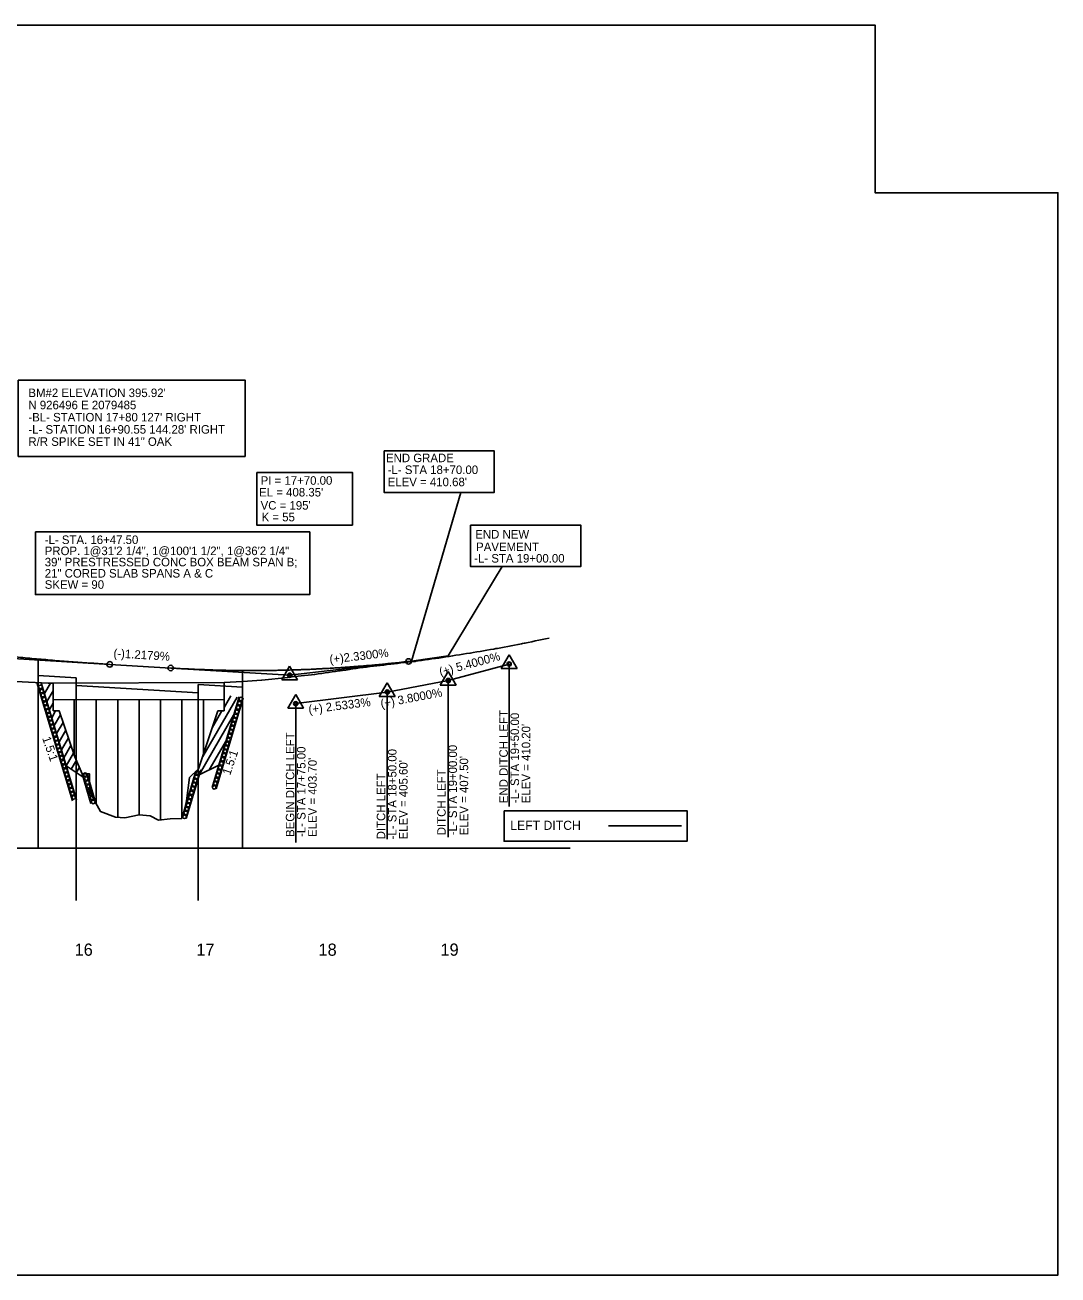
# Model space of a CAD drawing. Extents: x 573767 to 575255, y -54545 to -52045.
# Drawn here: x 574408 to 575255, y -53645 to -52620 of the extents above; entities that cross this region are included whole.
import ezdxf

# ---------------------------------------------------------------- set-up
doc = ezdxf.new("R2010")
doc.units = 0
for name, color, linetype in [('Default', 7, 'Continuous'), ('Exist Vertical Profile Ground Line', 7, 'Continuous'), ('Exist Vertical Profile Horizontal Axis Label Major', 7, 'Continuous'), ('Old_Level_2', 7, 'Continuous'), ('Old_Level_4', 7, 'Continuous'), ('Old_Level_63', 7, 'Continuous'), ('Prop Grid Mask', 7, 'Continuous'), ('Prop PFL Ditch Label CELL', 7, 'Continuous'), ('Prop PFL VPI Symbol CELL', 7, 'Continuous'), ('Prop Roadway Bridge', 7, 'Continuous'), ('Prop Vertical Profile Curve Label', 7, 'Continuous'), ('Prop Vertical Profile Ditch Grade Left', 7, 'Continuous'), ('Prop Vertical Profile Ditch Grade Left Label', 7, 'Continuous'), ('Prop Vertical Profile Grade', 7, 'Continuous'), ('Prop Vertical Profile Grade Label', 7, 'Continuous'), ('Prop VPI Ditch Grade Left Label', 7, 'Continuous'), ('Prop VPI Label', 7, 'Continuous'), ('Sheet Layout Profile Border', 7, 'Continuous')]:
    doc.layers.add(name, color=color, linetype=linetype)

msp = doc.modelspace()

# ---------------------------------------------------------------- linework, layer by layer
at = {"layer": 'Default'}
for p, q in [((574423.8, -53167.9), (574428.7, -53159.3)), ((574425.7, -53174.5), (574430.8, -53165.8)), ((574427.7, -53181.1), (574430.8, -53175.8)), ((574553.5, -53219.5), (574581.6, -53170.8)), ((574570.9, -53179.3), (574576.5, -53169.7)), ((574429.7, -53187.7), (574432.8, -53182.2)), ((574431.7, -53194.2), (574436.8, -53185.3)), ((574550.6, -53234.5), (574578.8, -53185.6)), ((574561.3, -53195.9), (574569.2, -53182.2)), ((574433.6, -53200.8), (574439, -53191.6)), ((574435.6, -53207.4), (574441.1, -53197.8)), ((574437.6, -53214), (574443.3, -53204.1)), ((574558.7, -53230.5), (574572.8, -53206.1)), ((574439.6, -53220.6), (574445.4, -53210.4)), ((574441.5, -53227.1), (574447.6, -53216.7)), ((574445.7, -53230), (574449.9, -53222.5)), ((574449.8, -53232.8), (574452.4, -53228.4)), ((574454, -53235.6), (574454.8, -53234.2))]:
    msp.add_line(p, q, dxfattribs=at)
at = {"layer": 'Exist Vertical Profile Ground Line'}
for p, q in [((574430.8, -53159.3), (574570.9, -53158.8)), ((574430.8, -53182.2), (574430.8, -53159.3)), ((574570.9, -53182.2), (574570.9, -53158.8)), ((574430.8, -53172.7), (574570.9, -53173)), ((574447.9, -53217.5), (574447.9, -53172.7)), ((574466.1, -53258.2), (574466.1, -53172.8)), ((574483.9, -53269.5), (574483.9, -53172.8)), ((574501.2, -53267.3), (574501.2, -53172.8)), ((574518.7, -53271.5), (574518.7, -53172.9)), ((574536.3, -53270.4), (574536.3, -53172.9)), ((574554.2, -53217.2), (574554.2, -53173))]:
    msp.add_line(p, q, dxfattribs=at)
for points in [[(574680.6, -53147.2), (574682.1, -53146.9), (574684.9, -53146.6), (574687.1, -53146.3), (574687.2, -53146.2), (574687.7, -53146.2), (574690.6, -53145.8), (574693.4, -53145.5), (574696.2, -53145.2), (574699, -53144.8), (574701.9, -53144.5), (574704.7, -53144.2), (574707.3, -53143.9), (574707.5, -53143.9), (574707.7, -53143.8), (574710.3, -53143.5), (574713.2, -53143.2), (574716, -53142.8), (574718.8, -53142.5), (574721.6, -53142.2), (574724.4, -53141.9), (574727.3, -53141.5), (574727.6, -53141.5), (574728.2, -53141.4), (574730.1, -53141.1), (574732.9, -53140.7), (574735.7, -53140.3), (574738.6, -53139.9), (574741.4, -53139.5), (574744.2, -53139.2), (574747, -53138.8), (574749.8, -53138.4), (574749.9, -53138.4), (574750.7, -53138.2), (574751.5, -53138.1), (574752.7, -53137.9), (574755.5, -53137.4), (574758.3, -53137), (574761.1, -53136.5), (574764, -53136.1), (574766.8, -53135.7), (574769.6, -53135.2), (574772.4, -53134.8), (574773.1, -53134.7), (574775.3, -53134.3), (574778.1, -53133.8), (574780.9, -53133.3), (574783.7, -53132.8), (574786.5, -53132.3), (574789.4, -53131.8), (574792.2, -53131.4), (574793.8, -53131.1), (574795, -53130.9), (574795.1, -53130.9), (574797.8, -53130.4), (574800.7, -53129.8), (574803.5, -53129.3), (574806.3, -53128.7), (574809.1, -53128.2), (574812, -53127.6), (574814.8, -53127.1), (574815.7, -53126.9), (574817, -53126.7), (574817.6, -53126.6), (574820.4, -53126), (574823.2, -53125.4), (574826.1, -53124.8), (574828.9, -53124.2), (574831.7, -53123.6), (574834.5, -53123), (574837.4, -53122.4)], [(574571.2, -53158.8), (574585.5, -53158), (574586.4, -53157.9), (574601.7, -53156.8), (574601.8, -53156.8), (574623.4, -53154.7), (574626.7, -53154.3), (574634.1, -53153.5), (574636.9, -53153.2), (574639.8, -53152.8), (574642.6, -53152.5), (574644.9, -53152.2), (574645, -53152.2), (574645.1, -53152.2), (574645.4, -53152.2), (574648.2, -53151.8), (574651.1, -53151.4), (574653.9, -53151), (574656.7, -53150.6), (574659.5, -53150.2), (574662.3, -53149.8), (574665.2, -53149.4), (574666.1, -53149.2), (574666.1, -53149.2), (574668, -53149), (574670.8, -53148.6), (574673.6, -53148.2), (574676.5, -53147.7), (574679.3, -53147.3), (574680.6, -53147.2)], [(574399.8, -53158.1), (574426.7, -53159.3), (574430.8, -53159.4)], [(574570.9, -53182.2), (574565.9, -53182.2), (574550.1, -53229.6), (574542.6, -53236.8), (574540.1, -53255.8), (574537.7, -53267.3), (574536.2, -53270.5), (574526.7, -53270.7), (574517.1, -53271.7), (574510.4, -53268.1), (574501.2, -53267.3), (574489.5, -53269.7), (574481.8, -53269.3), (574469.6, -53264.7), (574466.9, -53259.6), (574460.9, -53248.4), (574460.7, -53233.8), (574454.6, -53233.8), (574448.6, -53219.7), (574435.8, -53182.2), (574430.8, -53182.2)]]:
    msp.add_lwpolyline(points, dxfattribs=at)
at = {"layer": 'Old_Level_2'}
for centre in [(574420.4, -53162.5), (574421.4, -53165.9), (574422.4, -53169.2), (574423.4, -53172.6), (574424.3, -53175.9), (574583.5, -53175.8), (574584.6, -53172.4), (574425.4, -53179.1), (574426.4, -53182.2), (574427.4, -53185.4), (574428.3, -53188.5), (574580.5, -53186.2), (574581.5, -53182.8), (574582.6, -53179.3), (574429.2, -53191.7), (574430.1, -53195), (574431.1, -53198.3), (574577.6, -53196), (574578.5, -53192.6), (574579.5, -53189.4), (574432.1, -53201.5), (574433.2, -53205), (574434, -53208.1), (574573.6, -53209), (574574.6, -53205.7), (574575.6, -53202.5), (574576.6, -53199.1), (574435, -53211.3), (574436, -53214.3), (574436.9, -53217.5), (574570.9, -53218.4), (574571.8, -53215.3), (574572.7, -53212.2), (574437.8, -53220.6), (574439, -53224.2), (574440, -53227.6), (574567.7, -53228.6), (574568.8, -53225.2), (574569.8, -53221.8), (574441, -53231), (574441.9, -53234.2), (574442.9, -53237.4), (574457, -53234.4), (574458, -53237.6), (574547.4, -53239.4), (574548.3, -53236.3), (574549.4, -53233.1), (574564.8, -53238.5), (574565.8, -53235.1), (574566.8, -53231.9), (574443.8, -53240.7), (574444.9, -53243.7), (574445.8, -53246.9), (574446.6, -53250), (574458.9, -53240.8), (574459.8, -53244), (574460.8, -53247.1), (574461.7, -53250.2), (574544.3, -53249.3), (574545.4, -53245.7), (574546.4, -53242.5), (574562.9, -53244.8), (574563.8, -53241.6), (574447.6, -53253.1), (574462.8, -53253.5), (574463.7, -53256.8), (574541.5, -53259.4), (574542.4, -53256.1), (574543.3, -53252.8), (574538.5, -53268.9), (574539.5, -53265.8), (574540.5, -53262.6)]:
    msp.add_circle(centre, 1.5, dxfattribs=at)
at = {"layer": 'Old_Level_4'}
for p, q in [((574724.7, -53141.3), (574765.1, -53003)), ((574754.7, -53136.9), (574799, -53063.8))]:
    msp.add_line(p, q, dxfattribs=at)
for points in [[(574402.2, -52910.8), (574588.2, -52910.8), (574588.2, -52973.5), (574402.2, -52973.5)], [(574702.1, -52969), (574792.5, -52969), (574792.5, -53003), (574702.1, -53003)], [(574597.7, -52986.6), (574676.2, -52986.6), (574676.2, -53029.7), (574597.7, -53029.7)], [(574773.1, -53029.8), (574863.4, -53029.8), (574863.4, -53063.8), (574773.1, -53063.8)], [(574416.2, -53035.4), (574641.2, -53035.4), (574641.2, -53086.8), (574416.2, -53086.8)]]:
    msp.add_lwpolyline(points, close=True, dxfattribs=at)
at = {"layer": 'Old_Level_63'}
msp.add_line((573854.7, -53294.7), (574854.7, -53294.7), dxfattribs=at)
at = {"layer": 'Prop Grid Mask'}
msp.add_lwpolyline([(574800.6, -53264), (574950.6, -53264), (574950.6, -53289), (574800.6, -53289)], close=True, dxfattribs=at)
at = {"layer": 'Prop PFL Ditch Label CELL'}
msp.add_line((574886.1, -53276.3), (574946.1, -53276.3), dxfattribs=at)
at = {"layer": 'Prop PFL VPI Symbol CELL'}
for p, q in [((574624.7, -53145.5), (574618.2, -53156.7)), ((574624.7, -53145.5), (574631.2, -53156.7)), ((574804.7, -53136.2), (574798.2, -53147.4)), ((574804.7, -53136.2), (574811.2, -53147.4)), ((574804.7, -53260.6), (574804.7, -53143.7)), ((574754.7, -53149.7), (574748.2, -53160.9)), ((574754.7, -53149.7), (574761.2, -53160.9)), ((574798.2, -53147.4), (574811.2, -53147.4)), ((574618.2, -53156.7), (574631.2, -53156.7)), ((574704.7, -53159.2), (574698.2, -53170.4)), ((574704.7, -53159.2), (574711.2, -53170.4)), ((574704.7, -53166.7), (574704.7, -53287.3)), ((574748.2, -53160.9), (574761.2, -53160.9)), ((574754.7, -53157.2), (574754.7, -53285.7)), ((574629.7, -53168.7), (574623.2, -53179.9)), ((574629.7, -53168.7), (574636.2, -53179.9)), ((574629.7, -53176.2), (574629.7, -53290.1)), ((574698.2, -53170.4), (574711.2, -53170.4)), ((574623.2, -53179.9), (574636.2, -53179.9))]:
    msp.add_line(p, q, dxfattribs=at)
for centre, radius in [((574804.7, -53143.7), 1.75), ((574804.7, -53143.7), 1.2), ((574624.7, -53152.9), 1.75), ((574624.7, -53152.9), 1.2), ((574754.7, -53157.2), 1.75), ((574754.7, -53157.2), 1.2), ((574704.7, -53166.7), 1.75), ((574704.7, -53166.7), 1.2), ((574629.7, -53176.2), 1.75), ((574629.7, -53176.2), 1.2)]:
    msp.add_circle(centre, radius, dxfattribs=at)
at = {"layer": 'Prop Roadway Bridge'}
for p, q in [((574418.5, -53294.5), (574418.5, -53139.5)), ((574418.5, -53153), (574449.6, -53154.9)), ((574449.6, -53337.7), (574449.6, -53154.9)), ((574586, -53294.7), (574586, -53149)), ((574417.5, -53158.9), (574446.6, -53256)), ((574421.1, -53159), (574449.9, -53255.1)), ((574449.6, -53161.3), (574549.8, -53167.4)), ((574549.8, -53160.6), (574586, -53162.8)), ((574549.8, -53337.7), (574549.8, -53160.6)), ((574583.4, -53170.5), (574561.1, -53245)), ((574586.7, -53171.5), (574564.4, -53246)), ((574455.3, -53236.4), (574441.6, -53227.3)), ((574550.6, -53234.5), (574566.2, -53226.8)), ((574454.5, -53233.8), (574461.8, -53258.2)), ((574458.6, -53233.7), (574465.9, -53258.1)), ((574547.9, -53231.5), (574536.2, -53270.5)), ((574551.8, -53230.4), (574539.8, -53270.5))]:
    msp.add_line(p, q, dxfattribs=at)
at = {"layer": 'Prop Vertical Profile Curve Label'}
for centre in [(574477.2, -53144), (574527.2, -53147), (574722.2, -53141.6)]:
    msp.add_circle(centre, 2.25, dxfattribs=at)
at = {"layer": 'Prop Vertical Profile Ditch Grade Left'}
for p, q in [((574754.7, -53157.2), (574804.7, -53143.7)), ((574629.7, -53176.2), (574704.7, -53166.7)), ((574704.7, -53166.7), (574754.7, -53157.2))]:
    msp.add_line(p, q, dxfattribs=at)
at = {"layer": 'Prop Vertical Profile Grade'}
for p, q in [((574477.2, -53144), (574527.2, -53147)), ((574722.2, -53141.6), (574724.7, -53141.3)), ((574754.7, -53136.9), (574724.7, -53141.3))]:
    msp.add_line(p, q, dxfattribs=at)
for points in [[(574102.2, -53089.7), (574109.7, -53091.4), (574117.2, -53093), (574124.7, -53094.7), (574132.2, -53096.3), (574139.7, -53097.9), (574147.2, -53099.5), (574154.7, -53101), (574162.2, -53102.6), (574169.7, -53104.1), (574177.2, -53105.6), (574184.7, -53107), (574192.2, -53108.4), (574199.7, -53109.8), (574207.2, -53111.2), (574214.7, -53112.6), (574222.2, -53113.9), (574229.7, -53115.2), (574237.2, -53116.5), (574244.7, -53117.7), (574252.2, -53118.9), (574259.7, -53120.1), (574267.2, -53121.3), (574274.7, -53122.5), (574282.2, -53123.6), (574289.7, -53124.7), (574297.2, -53125.8), (574304.7, -53126.8), (574312.2, -53127.8), (574319.7, -53128.8), (574327.2, -53129.8), (574334.7, -53130.7), (574342.2, -53131.7), (574349.7, -53132.6), (574357.2, -53133.4), (574364.7, -53134.3), (574372.2, -53135.1), (574379.7, -53135.9), (574387.2, -53136.7), (574394.7, -53137.4), (574402.2, -53138.1), (574409.7, -53138.8), (574417.2, -53139.5), (574424.7, -53140.1), (574432.2, -53140.8), (574439.7, -53141.4), (574447.2, -53141.9), (574454.7, -53142.5), (574462.2, -53143), (574469.7, -53143.5), (574477.2, -53144)], [(574527.2, -53147), (574531.1, -53147.2), (574535, -53147.5), (574538.9, -53147.7), (574542.8, -53147.8), (574546.7, -53148), (574550.6, -53148.2), (574554.5, -53148.3), (574558.4, -53148.5), (574562.3, -53148.6), (574566.2, -53148.7), (574570.1, -53148.8), (574574, -53148.9), (574577.9, -53148.9), (574581.8, -53149), (574585.7, -53149), (574589.6, -53149), (574593.5, -53149), (574597.4, -53149), (574601.3, -53149), (574605.2, -53149), (574609.1, -53148.9), (574613, -53148.9), (574616.9, -53148.8), (574620.8, -53148.7), (574624.7, -53148.6), (574628.6, -53148.5), (574632.5, -53148.4), (574636.4, -53148.2), (574640.3, -53148.1), (574644.2, -53147.9), (574648.1, -53147.7), (574652, -53147.5), (574655.9, -53147.3), (574659.8, -53147.1), (574663.7, -53146.8), (574667.6, -53146.6), (574671.5, -53146.3), (574675.4, -53146), (574679.3, -53145.7), (574683.2, -53145.4), (574687.1, -53145.1), (574691, -53144.8), (574694.9, -53144.4), (574698.8, -53144.1), (574702.7, -53143.7), (574706.6, -53143.3), (574710.5, -53142.9), (574714.4, -53142.5), (574718.3, -53142), (574722.2, -53141.6)]]:
    msp.add_spline(points, degree=3, dxfattribs=at)
at = {"layer": 'Prop VPI Ditch Grade Left Label'}
for centre in [(574704.7, -53166.7), (574754.7, -53157.2)]:
    msp.add_circle(centre, 0.5, dxfattribs=at)
at = {"layer": 'Prop VPI Label'}
for p, q in [((574477.2, -53144), (574289.7, -53132.5)), ((574722.2, -53141.6), (574624.7, -53152.9)), ((574527.2, -53147), (574624.7, -53152.9))]:
    msp.add_line(p, q, dxfattribs=at)
at = {"layer": 'Sheet Layout Profile Border'}
msp.add_lwpolyline([(573854.7, -52619.7), (573854.7, -53644.7), (575254.7, -53644.7), (575254.7, -52757.2), (575104.7, -52757.2), (575104.7, -52619.7)], close=True, dxfattribs=at)

# ---------------------------------------------------------------- texts
at = {"layer": 'Exist Vertical Profile Horizontal Axis Label Major'}
for s, p in [('16', (574448.4, -53382.9)), ('17', (574548.2, -53382.9)), ('18', (574648.4, -53382.9)), ('19', (574748.4, -53382.9))]:
    msp.add_text(s, height=10, dxfattribs=at).set_placement(p)
at = {"layer": 'Prop PFL Ditch Label CELL'}
msp.add_text('LEFT DITCH', height=7.49, dxfattribs=at).set_placement((574805.6, -53279.7))
at = {"layer": 'Prop PFL VPI Symbol CELL'}
for s, p in [('END DITCH LEFT', (574803.6, -53257.8)), ('-L- STA 19+50.00', (574812.8, -53257.8)), ("ELEV = 410.20'", (574822, -53257.8)), ('BEGIN DITCH LEFT', (574628.6, -53285.5)), ('-L- STA 17+75.00', (574637.7, -53285.5)), ('-L- STA 18+50.00', (574712.3, -53287.5)), ('-L- STA 19+00.00', (574761.9, -53284.1)), ("ELEV = 403.70'", (574646.9, -53285.5)), ("ELEV = 405.60'", (574721.4, -53287.5)), ("ELEV = 407.50'", (574771.1, -53284.1)), ('DITCH LEFT', (574703.1, -53287.5)), ('DITCH LEFT', (574752.7, -53284.1))]:
    msp.add_text(s, height=7, rotation=90, dxfattribs=at).set_placement(p)
at = {"layer": 'Prop Vertical Profile Curve Label'}
for s, p in [("BM#2 ELEVATION 395.92'", (574410.5, -52924.8)), ('N 926496 E 2079485', (574410.5, -52934.8)), ("-BL- STATION 17+80 127' RIGHT", (574410.5, -52944.8)), ("-L- STATION 16+90.55 144.28' RIGHT", (574410.5, -52954.8)), ('R/R SPIKE SET IN 41" OAK', (574410.5, -52964.8)), ('END GRADE', (574703.7, -52978.2)), ('-L- STA 18+70.00', (574705.1, -52987.9)), ("ELEV = 410.68'", (574705.1, -52997.9)), ("VC = 195'", (574600.9, -53017.1)), ('K = 55', (574601.7, -53026.7)), ('END NEW', (574776.9, -53040.8)), ('-L- STA 19+00.00', (574776, -53060.5)), ('PAVEMENT', (574777.6, -53051.1))]:
    msp.add_text(s, height=7, dxfattribs=at).set_placement(p)
at = {"layer": 'Prop Vertical Profile Ditch Grade Left Label'}
for s, rotation, p in [('(+) 5.4000%', 15.1096, (574748.4, -53153.7)), ('(+) 3.8000%', 10.758, (574699.9, -53179.7)), ('(+) 2.5333%', 7.219, (574640.6, -53184.5))]:
    msp.add_text(s, height=7, rotation=rotation, dxfattribs=at).set_placement(p)
at = {"layer": 'Prop Vertical Profile Grade Label'}
for s, rotation, p in [('(-)1.2179%', 356.5152, (574480.1, -53138.2)), ('(+)2.3300%', 6.645, (574657.8, -53143.4)), ('1.5:1', 289.1646, (574421.7, -53204.5)), ('1.5:1', 70.9143, (574575.9, -53235.3))]:
    msp.add_text(s, height=7, rotation=rotation, dxfattribs=at).set_placement(p)
at = {"layer": 'Prop VPI Label'}
for s, p in [('PI = 17+70.00', (574600.9, -52996.7)), ("EL = 408.35'", (574599.7, -53006.3)), ('-L- STA. 16+47.50', (574423.9, -53045.3)), ('PROP. 1@31\'2 1/4", 1@100\'1 1/2", 1@36\'2 1/4"', (574423.9, -53054.4)), ('39" PRESTRESSED CONC BOX BEAM SPAN B;', (574423.9, -53063.6)), ('21" CORED SLAB SPANS A & C', (574423.9, -53072.8)), ('SKEW = 90', (574423.9, -53082))]:
    msp.add_text(s, height=7, dxfattribs=at).set_placement(p)

doc.saveas('drawing.dxf')
